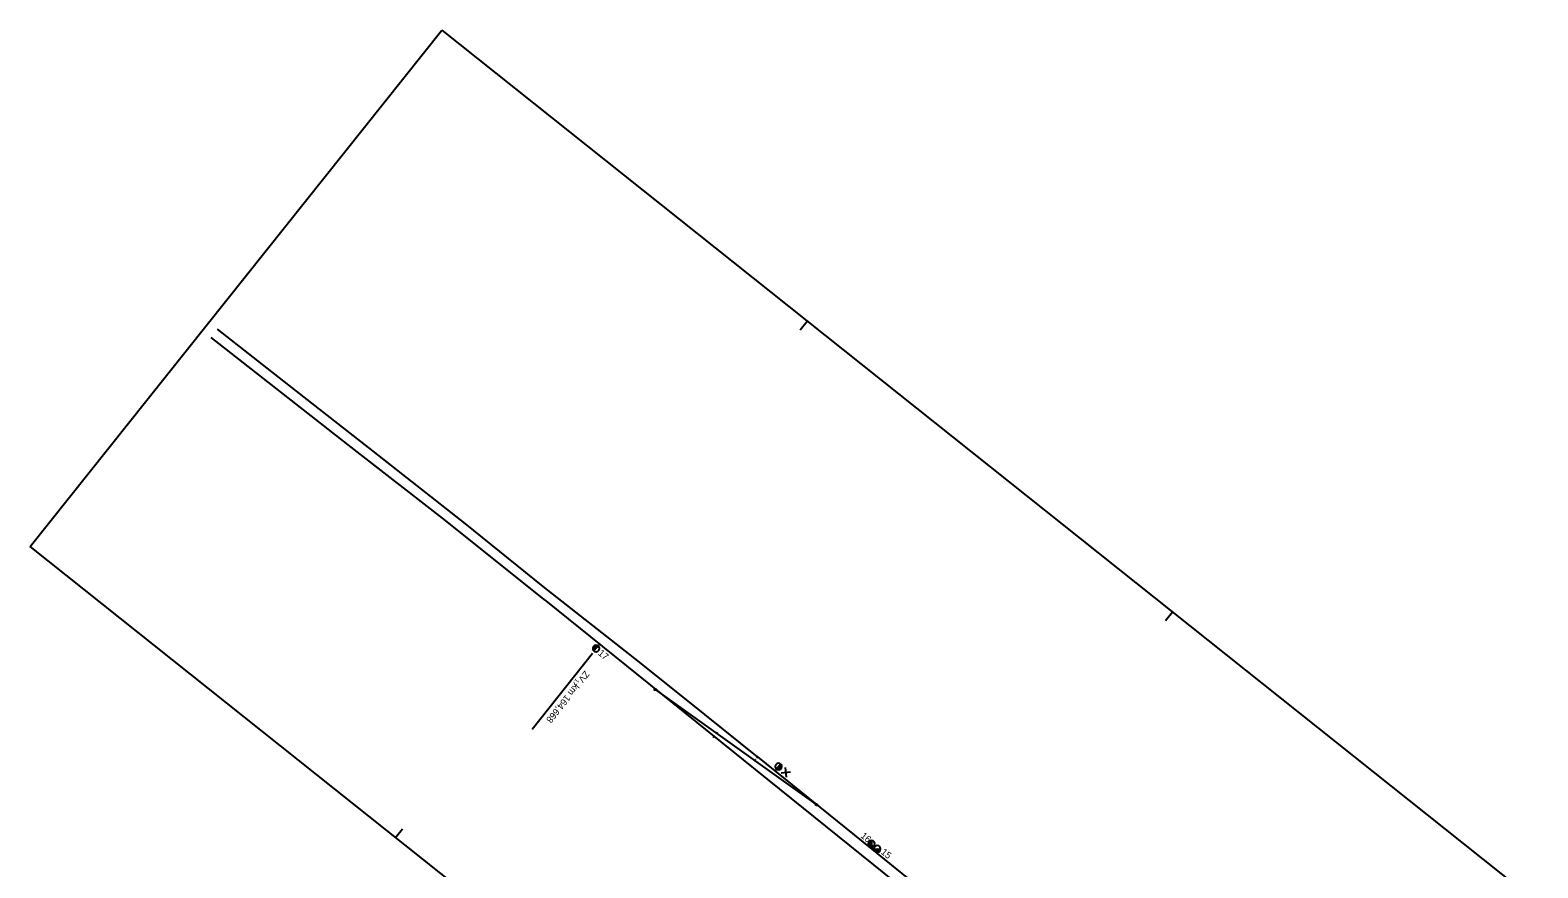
# Model space of a CAD drawing. Extents: x -481120 to -479270, y -1317564 to -1316014.
# Drawn here: x -481120 to -480442, y -1316391 to -1316014 of the extents above; entities that cross this region are included whole.
import ezdxf

# ---------------------------------------------------------------- set-up
doc = ezdxf.new("R2010")
doc.units = 0
for name, color, linetype in [('kolaj s', 7, 'Continuous'), ('Level 61', 7, 'Continuous'), ('popis 35', 7, 'Continuous')]:
    doc.layers.add(name, color=color, linetype=linetype)

msp = doc.modelspace()

# ---------------------------------------------------------------- linework, layer by layer
at = {"layer": 'kolaj s'}
for p, q in [((-481003.43, -1316174.11), (-481035.46, -1316148.91)), ((-480976.69, -1316200.91), (-481038.36, -1316152.58)), ((-480967.61, -1316202.07), (-481003.43, -1316174.11)), ((-480933.02, -1316234.97), (-480976.69, -1316200.91)), ((-480924.18, -1316236.23), (-480967.61, -1316202.07)), ((-480888.64, -1316270.51), (-480933.02, -1316234.97)), ((-480889.02, -1316264.58), (-480924.18, -1316236.23)), ((-480847.93, -1316297.06), (-480889.02, -1316264.58)), ((-480888.64, -1316270.51), (-480699.16, -1316423.18)), ((-480824.02, -1316316.1), (-480847.93, -1316297.06)), ((-480838.73, -1316310.91), (-480766.32, -1316362.7)), ((-480838.71, -1316310.95), (-480838.71, -1316310.95)), ((-480792.68, -1316341.29), (-480824.02, -1316316.1)), ((-480812.72, -1316332.61), (-480812.05, -1316331.87)), ((-480812.39, -1316332.24), (-480812.39, -1316332.24)), ((-480811.31, -1316330.9), (-480810.64, -1316330.16)), ((-480810.98, -1316330.53), (-480810.98, -1316330.53)), ((-480793, -1316341.7), (-480792.33, -1316340.95)), ((-480794.16, -1316343.07), (-480793.49, -1316342.33)), ((-480793.83, -1316342.7), (-480793.83, -1316342.7)), ((-480792.68, -1316341.29), (-480741.34, -1316382.82)), ((-480792.66, -1316341.33), (-480792.66, -1316341.33)), ((-480784.81, -1316347.53), (-480782.32, -1316344.46)), ((-480784.81, -1316347.53), (-480784.81, -1316347.53)), ((-480766.29, -1316362.74), (-480766.29, -1316362.74)), ((-480741.34, -1316382.82), (-480709, -1316408.98))]:
    msp.add_line(p, q, dxfattribs=at)
for points in [[(-480838.45, -1316310.65), (-480838.32, -1316311.03), (-480838.57, -1316311.33), (-480838.97, -1316311.26), (-480839.1, -1316310.88), (-480838.84, -1316310.58), (-480838.45, -1316310.65)], [(-480782.01, -1316344.72), (-480782.63, -1316344.21), (-480783.39, -1316344.09), (-480784.1, -1316344.37), (-480784.61, -1316344.98), (-480784.72, -1316345.75), (-480784.46, -1316346.46), (-480783.83, -1316346.96), (-480783.08, -1316347.08), (-480782.36, -1316346.82), (-480781.86, -1316346.2), (-480781.74, -1316345.43), (-480782.01, -1316344.72), (-480781.97, -1316345.06), (-480782.36, -1316344.76), (-480782.55, -1316344.99), (-480781.89, -1316345.52), (-480781.96, -1316345.85), (-480782.74, -1316345.22), (-480782.93, -1316345.45), (-480782.03, -1316346.18), (-480782.22, -1316346.41), (-480783.12, -1316345.68), (-480783.31, -1316345.92), (-480782.41, -1316346.64), (-480782.72, -1316346.78), (-480783.5, -1316346.15), (-480783.68, -1316346.38), (-480783.02, -1316346.92), (-480783.52, -1316346.9), (-480783.88, -1316346.62)], [(-480766.03, -1316362.43), (-480765.89, -1316362.81), (-480766.15, -1316363.11), (-480766.55, -1316363.04), (-480766.68, -1316362.66), (-480766.42, -1316362.36), (-480766.03, -1316362.43)]]:
    msp.add_lwpolyline(points, dxfattribs=at)
at = {"layer": 'Level 61'}
for p, q in [((-481119.71, -1316246.64), (-480934.65, -1316014.34)), ((-480934.65, -1316014.34), (-480441.9, -1316406.9)), ((-480773.52, -1316149.11), (-480770.4, -1316145.2)), ((-480626.96, -1316639.2), (-481119.71, -1316246.64)), ((-480609.27, -1316279.96), (-480606.15, -1316276.05)), ((-480955.46, -1316377.49), (-480952.35, -1316373.58))]:
    msp.add_line(p, q, dxfattribs=at)
at = {"layer": 'popis 35'}
for p, q in [((-480863.59, -1316290.63), (-480866.24, -1316293.56)), ((-480863.59, -1316290.63), (-480863.59, -1316290.63)), ((-480866.87, -1316294.78), (-480893.95, -1316329.01)), ((-480780.21, -1316346.12), (-480779.77, -1316350.37)), ((-480782.12, -1316348.46), (-480777.87, -1316348.02)), ((-480741.34, -1316382.82), (-480741.34, -1316382.82))]:
    msp.add_line(p, q, dxfattribs=at)
for points in [[(-480866.53, -1316293.29), (-480865.94, -1316293.83), (-480865.19, -1316293.98), (-480864.46, -1316293.75), (-480863.92, -1316293.16), (-480863.77, -1316292.41), (-480864.02, -1316291.65), (-480864.58, -1316291.15), (-480865.34, -1316290.99), (-480866.07, -1316291.22), (-480866.61, -1316291.81), (-480866.76, -1316292.56), (-480866.53, -1316293.29), (-480866.55, -1316292.94), (-480866.18, -1316293.28), (-480865.98, -1316293.05), (-480866.61, -1316292.48), (-480866.56, -1316292.13), (-480865.78, -1316292.83), (-480865.58, -1316292.61), (-480866.43, -1316291.84), (-480866.23, -1316291.61), (-480865.38, -1316292.38), (-480865.18, -1316292.16), (-480866.03, -1316291.39), (-480865.72, -1316291.27), (-480864.97, -1316291.94), (-480864.77, -1316291.72), (-480865.4, -1316291.15), (-480864.91, -1316291.19), (-480864.57, -1316291.49)], [(-480741.39, -1316381.85), (-480740.65, -1316381.61), (-480740.13, -1316381.03), (-480739.97, -1316380.27), (-480740.21, -1316379.53), (-480740.78, -1316379.01), (-480741.54, -1316378.85), (-480742.28, -1316379.09), (-480742.8, -1316379.67), (-480742.96, -1316380.43), (-480742.73, -1316381.17), (-480742.15, -1316381.69), (-480741.39, -1316381.85), (-480741.55, -1316381.49), (-480742.18, -1316381.52), (-480742.48, -1316381.25), (-480741.63, -1316381.21), (-480741.61, -1316380.89), (-480742.64, -1316380.98), (-480742.76, -1316380.67), (-480741.63, -1316380.61), (-480741.64, -1316380.33), (-480742.81, -1316380.35), (-480742.75, -1316380.06), (-480741.62, -1316380.01), (-480741.64, -1316379.72), (-480742.63, -1316379.77), (-480742.4, -1316379.44), (-480741.69, -1316379.41), (-480741.67, -1316379.09), (-480742.02, -1316379.11)], [(-480741.54, -1316378.87), (-480741.34, -1316382.82), (-480737.38, -1316382.62)], [(-480737.37, -1316382.62), (-480737.61, -1316381.88), (-480738.18, -1316381.36), (-480738.99, -1316381.2), (-480739.68, -1316381.44), (-480740.2, -1316382.01), (-480740.36, -1316382.77), (-480740.12, -1316383.51), (-480739.55, -1316384.03), (-480738.83, -1316384.2), (-480738.05, -1316383.95), (-480737.53, -1316383.38), (-480737.37, -1316382.62), (-480737.69, -1316382.81), (-480737.67, -1316383.31), (-480737.97, -1316383.64), (-480738.01, -1316382.86), (-480738.29, -1316382.88), (-480738.24, -1316383.87), (-480738.55, -1316383.99), (-480738.61, -1316382.86), (-480738.93, -1316382.91), (-480738.83, -1316384), (-480739.15, -1316383.98), (-480739.21, -1316382.93), (-480739.49, -1316382.94), (-480739.44, -1316383.93), (-480739.77, -1316383.63), (-480739.81, -1316382.92), (-480740.09, -1316382.93), (-480740.07, -1316383.36)]]:
    msp.add_lwpolyline(points, dxfattribs=at)

# ---------------------------------------------------------------- texts
for s, height, rotation, p in [('17', 3, 320.95676, (-480864.66, -1316295.09)), ('ZV  km 164,668', 3, 231.65676, (-480870.34, -1316302.29)), ('17', 2, 231.65676, (-480874.2, -1316305.83)), ('16', 3, 320.95676, (-480746.6, -1316377.27)), ('15', 3, 320.95676, (-480737.48, -1316384.57))]:
    msp.add_text(s, height=height, rotation=rotation, dxfattribs=at).set_placement(p)

doc.saveas('drawing.dxf')
